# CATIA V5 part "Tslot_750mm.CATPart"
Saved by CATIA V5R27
Part number: Tslot_750mm
Bounding box of the stored display mesh (mm): x -19.056 to 19.056, y -19.056 to 19.056, z -1524 to -774
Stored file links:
  \\triton.meca.polymtl.ca\usagers\zaoue\profiles\Desktop\varm_ass\structure prismatique\Tslot_750mm.CATPart
  \\triton.meca.polymtl.ca\usagers\zaoue\profiles\Desktop\Clean_varm_CAD-20230123T141814Z-001\Clean_varm_CAD\Alu_Tslot_44in.CATPart
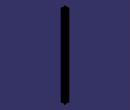
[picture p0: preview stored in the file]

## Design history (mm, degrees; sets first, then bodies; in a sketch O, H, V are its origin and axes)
Body1 (main body)
Body2 "Boss-Extrude1"
  Solid1: solid without history
  Sketch1 on face of Solid1, origin (0, 0, 1524), H (1, 0, 0), V (0, 1, 0)
    line L1 (-31.855, 32.792) -> (28.107, 32.792)
    line L2 (28.107, 32.792) -> (28.107, -28.509)
    line L3 (28.107, -28.509) -> (-31.855, -28.509)
    line L4 (-31.855, -28.509) -> (-31.855, 32.792)
    horizontal: L1 H, L3 H
    vertical: L2 V, L4 V
    fix: L1, L2, L3, L4
  Pocket1: profile Sketch1, direction (0, 0, -1), length 2298
  Sketch2 on end face of Pocket1, origin (0, 0, -774), H (1, 0, 0), V (0, 1, 0)
    line L1 (19.05, -7.9756) -> (19.05, -9.4996)
    arc A1 centre (19.05, -8.7376) radius 0.762 from (19.05, -7.9756) to (19.05, -9.4996) ccw
    point P3 (19.05, -8.7376)
    reference projected arc E1 centre (19.05, -8.7376) radius 0.762 from (19.05, -7.9756) to (18.288, -8.7376) ccw from edge [end face of Pocket1 | face of Solid1]
    reference projected arc E2 centre (19.05, -8.7376) radius 0.762 from (19.05, -7.9756) to (18.288, -8.7376) ccw from edge [end face of Pocket1 | face of Solid1]
    reference projected arc E3 centre (19.05, -8.7376) radius 0.762 from (19.05, -7.9756) to (18.288, -8.7376) ccw from edge [end face of Pocket1 | face of Solid1]
    line L2 (19.0564, 15.8623) -> (19.0564, 14.3256)
    point P4 (19.0564, 15.0939)
    arc A2 centre (19.0564, 15.0939) radius 0.7684 from (19.0564, 15.8623) to (19.0564, 14.3256) ccw
    line L3 (19.0564, -14.3256) -> (19.0564, -15.8623)
    point P7 (19.0564, -15.0939)
    line L4 (19.05, 9.4996) -> (19.05, 7.9756)
    point P8 (19.05, 8.7376)
    arc A3 centre (19.0564, -15.0939) radius 0.7684 from (19.0564, -14.3256) to (19.0564, -15.8623) ccw
    arc A4 centre (19.05, 8.7376) radius 0.762 from (19.05, 9.4996) to (19.05, 7.9756) ccw
    reference projected arc E4 centre (19.0564, -15.0939) radius 0.7684 from (19.05, -14.3256) to (18.288, -15.0939) ccw from edge [end face of Pocket1 | face of Solid1]
    reference projected arc E5 centre (19.0564, -15.0939) radius 0.7684 from (19.05, -14.3256) to (18.288, -15.0939) ccw from edge [end face of Pocket1 | face of Solid1]
    reference projected arc E6 centre (19.05, 8.7376) radius 0.762 from (19.05, 9.4996) to (18.288, 8.7376) ccw from edge [end face of Pocket1 | face of Solid1]
    reference projected arc E7 centre (19.05, 8.7376) radius 0.762 from (19.05, 9.4996) to (18.288, 8.7376) ccw from edge [end face of Pocket1 | face of Solid1]
    reference projected arc E8 centre (19.0564, 15.0939) radius 0.7684 from (19.05, 15.8623) to (18.288, 15.0939) ccw from edge [end face of Pocket1 | face of Solid1]
    reference projected arc E9 centre (19.0564, 15.0939) radius 0.7684 from (19.05, 15.8623) to (18.288, 15.0939) ccw from edge [end face of Pocket1 | face of Solid1]
    line L5 (14.3256, -19.0563) -> (15.8623, -19.0563)
    arc A5 centre (15.0939, -19.0563) radius 0.7684 from (15.8623, -19.0563) to (14.3256, -19.0563) ccw
    point P15 (15.0939, -19.0563)
    line L6 (-15.8623, -19.0563) -> (-14.3256, -19.0563)
    point P16 (-15.0939, -19.0563)
    arc A6 centre (-15.0939, -19.0563) radius 0.7684 from (-14.3256, -19.0563) to (-15.8623, -19.0563) ccw
    line L7 (7.9756, -19.05) -> (9.4996, -19.05)
    point P19 (8.7376, -19.05)
    arc A7 centre (8.7376, -19.05) radius 0.762 from (9.4996, -19.05) to (7.9756, -19.05) ccw
    line L8 (-9.4996, -19.05) -> (-7.9756, -19.05)
    point P22 (-8.7376, -19.05)
    arc A8 centre (-8.7376, -19.05) radius 0.762 from (-7.9756, -19.05) to (-9.4996, -19.05) ccw
    reference projected arc E10 centre (-15.0939, -19.0563) radius 0.7684 from (-14.3256, -19.05) to (-15.8623, -19.05) ccw from edge [end face of Pocket1 | face of Solid1]
    reference projected arc E11 centre (-15.0939, -19.0563) radius 0.7684 from (-14.3256, -19.05) to (-15.8623, -19.05) ccw from edge [end face of Pocket1 | face of Solid1]
    reference projected arc E12 centre (15.0939, -19.0563) radius 0.7684 from (15.8623, -19.05) to (14.3256, -19.05) ccw from edge [end face of Pocket1 | face of Solid1]
    reference projected arc E13 centre (15.0939, -19.0563) radius 0.7684 from (15.8623, -19.05) to (14.3256, -19.05) ccw from edge [end face of Pocket1 | face of Solid1]
    reference projected arc E14 centre (15.0939, -19.0563) radius 0.7684 from (15.8623, -19.05) to (14.3256, -19.05) ccw from edge [end face of Pocket1 | face of Solid1]
    reference projected arc E15 centre (8.7376, -19.05) radius 0.762 from (9.4996, -19.05) to (7.9756, -19.05) ccw from edge [end face of Pocket1 | face of Solid1]
    reference projected arc E16 centre (8.7376, -19.05) radius 0.762 from (9.4996, -19.05) to (7.9756, -19.05) ccw from edge [end face of Pocket1 | face of Solid1]
    reference projected arc E17 centre (-8.7376, -19.05) radius 0.762 from (-7.9756, -19.05) to (-9.4996, -19.05) ccw from edge [end face of Pocket1 | face of Solid1]
    reference projected arc E18 centre (-8.7376, -19.05) radius 0.762 from (-7.9756, -19.05) to (-9.4996, -19.05) ccw from edge [end face of Pocket1 | face of Solid1]
    construction line L9 (0, 0) -> (35.726, 0)
    construction line L10 (0, 0) -> (0, -21.547)
    radius A1 = 0.762
    radius E3 = 0.762 (reference)
    vertical: L1 V, L2 V, L3 V, L4 V, L10 V
    midpoint: P3 L1, P4 L2, P7 L3, P8 L4, P15 L5, P16 L6, P19 L7, P22 L8
    coincidence: A1 E1, A3 E4, A4 E6, A2 E8, A6 E10, A5 E14, A7 E15, A8 E17
    concentricity: A1 E2, A3 E5, A4 E7, A2 E9, A6 E11, A5 E12, A5 E13, A7 E16, A8 E18
    horizontal: L5 H, L6 H, L7 H, L8 H, L9 H
  Pad1: profile Sketch2, direction (0, 0, -1), up to face of Solid1
  Mirror1: of Pad1, about {plane type Offset, RefPlane face of Solid1, Offset 19.05}
  Mirror2: of Pad1, about {plane type Offset, RefPlane face of Solid1, Offset 19.05}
